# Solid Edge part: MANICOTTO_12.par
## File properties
Subject: MANICOTTO_12
Author: Francesco
Template: Normal.par
Last saved by: f_grande
Revision: 3
Application: Solid Edge
Material: Alluminio, 1060
Stile della faccia: Alluminio
Stile di riempimento: ANSI38(Alluminio)
Stile virtuale: Alluminio lucidato
Coef. of Thermal Exp: 0.0
Thermal Conductivity: 221.0
Specific Heat: 920.0
Modulus of Elasticity: 68947570000.0
Poisson's Ratio: 0.33
Yield Stress: 27579028.0
Ultimate Stress: 68947570.0
Elongation: 0.0
Tipo di contenuto documento: 0
Densità: 2712,000 kg/m^3
Precisione: 0,990
Document Number: KR0130
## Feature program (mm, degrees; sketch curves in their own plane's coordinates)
sketch for "unnamed Protrusion 1" plane through (0, 0, 0) normal (0, -1, 0) x-axis (1, 0, 0)
  line (-13.0756, 7.3215) -> (7.9244, 7.3215)
  line (7.9244, 7.3215) -> (7.9244, -7.5985)
  line (7.9244, -7.5985) -> (6.9244, -7.5985)
  line (6.9244, -7.5985) -> (6.9244, -16.0985)
  line (6.9244, -16.0985) -> (-2.0756, -16.0985)
  line (-2.0756, -16.0985) -> (-2.0756, -20.3785)
  line (-2.0756, -20.3785) -> (-13.0756, -20.3785)
  line (-13.0756, -20.3785) -> (-13.0756, 7.3215)
  dimension (linear) = 6.9244
  dimension (linear) = 2.0756
  dimension (linear) = 2.0756
extrude "unnamed Protrusion 1" add finite 70.1 along -normal
body pattern "unnamed BodyPattern 1"
pattern "unnamed Pattern 1"
chamfer "Smusso_1" setback 1
sketch for "unnamed Cutout 1" plane through (-13.0756, 0, -6.5285) normal (0, -1, 0) x-axis (1, 0, 0)
  line (0, 13.85) -> (6.5, 13.85)
  line (6.5, 13.85) -> (6.5, 13.35)
  line (6.5, 13.35) -> (-6.5, 13.35)
  line (-6.5, 13.35) -> (-6.5, 13.85)
  line (-6.5, 13.85) -> (0, 13.85)
  dimension (linear) = 6.5
extrude "unnamed Cutout 1" cut to key point along -normal
chamfer "Smusso_2" setback 0.5
chamfer "Smusso_3" setback 4.28
sketch for "Foro_1" plane through (-27.0756, 35.05, 7.3215) normal (0, 0, 1) x-axis (0, 1, 0)
  hole centre (25, 1) bore radius 2
hole "Foro_1" diameter 4 through
sketch for "unnamed Hole 1" plane through (-27.0756, 35.05, 7.3215) normal (0, 0, 1) x-axis (0, 1, 0)
  hole centre (25, -29) bore radius 2
hole "unnamed Hole 1" through
sketch for "unnamed Hole 2" plane through (-27.0756, 35.05, 7.3215) normal (0, 0, 1) x-axis (0, 1, 0)
  hole centre (-25, -29) bore radius 2
hole "unnamed Hole 2" through
sketch for "unnamed Hole 3" plane through (-27.0756, 35.05, 7.3215) normal (0, 0, 1) x-axis (0, 1, 0)
  hole centre (-25, 1) bore radius 2
  dimension (linear) = 25
hole "unnamed Hole 3" through
pattern "unnamed Pattern 2" of "Foro_1", "unnamed Hole 1", "unnamed Hole 2", "unnamed Hole 3"
sketch for "Foro_5" plane through (-13.0756, 0, -6.5285) normal (0, -1, 0) x-axis (1, 0, 0)
  hole centre (0, -1.25) bore radius 6
hole "Foro_5" diameter 12 through
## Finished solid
Body 1: solid body, 23 faces, 58 edges, 32 vertices.
  Faces by surface: plane 18, cylinder 5
  Edges by curve: line 48, circle 10
Bounding box of the edges (mm): 42.000 x 70.100 x 27.700, from (-34.0756, 0, -20.3785) to (7.9244, 70.1, 7.3215).
Cylindrical faces by radius (mm): R2 x4, R6 x1
Planar faces by outward normal: +x 2, +y 1, +z 3, -x 2, -y 1, -z 3, oblique 6
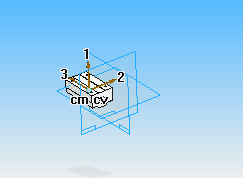
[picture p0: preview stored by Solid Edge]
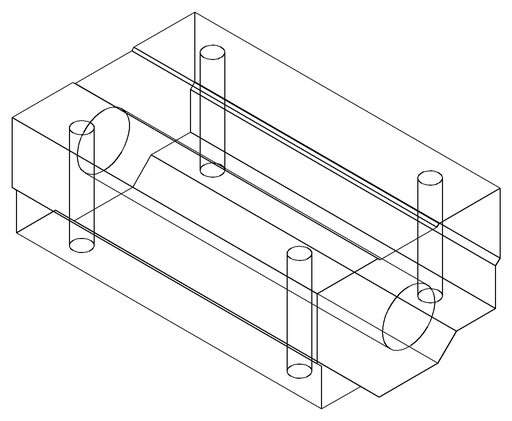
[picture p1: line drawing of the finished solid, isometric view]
